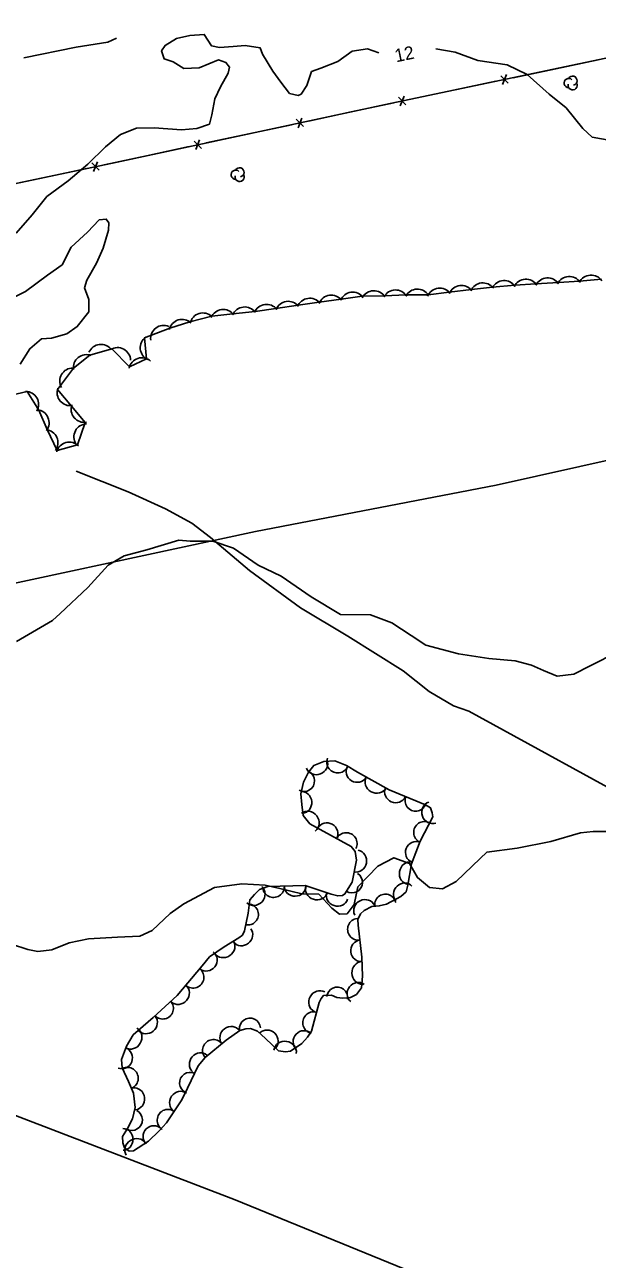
# Model space of a CAD drawing. Extents: x 643342 to 646936, y 5873857 to 5876103.
# Drawn here: x 645445.8 to 645577.3, y 5875329 to 5875612.3 of the extents above; entities that cross this region are included whole.
import ezdxf

# ---------------------------------------------------------------- set-up
doc = ezdxf.new("R2010")
doc.units = 0
for name, color, linetype in [('Niveau 1', 7, 'Continuous'), ('Niveau 2', 7, 'Continuous'), ('Niveau 22', 7, 'Continuous'), ('Niveau 37', 7, 'Continuous'), ('Niveau 4', 7, 'Continuous'), ('Niveau 44', 7, 'Continuous')]:
    doc.layers.add(name, color=color, linetype=linetype)

msp = doc.modelspace()

# ---------------------------------------------------------------- linework, layer by layer
at = {"layer": 'Niveau 1'}
msp.add_lwpolyline([(645443.92, 5875470.79), (645452.23, 5875475.56), (645453.99, 5875477.23), (645460.28, 5875483.15), (645464.96, 5875488.29), (645468.64, 5875490.43), (645473.89, 5875491.77), (645481.2, 5875494), (645483.82, 5875493.82), (645489.02, 5875493.82), (645493.78, 5875492.21), (645499.44, 5875488.28), (645504.69, 5875485.78), (645511.57, 5875481.04), (645518.29, 5875476.93), (645525.21, 5875476.91), (645530.11, 5875475.02), (645534.58, 5875472.16), (645537.95, 5875469.95), (645545.39, 5875467.94), (645552.41, 5875466.89), (645558.39, 5875466.32), (645562.17, 5875465.38), (645564.93, 5875464.11), (645568.04, 5875462.82), (645571.86, 5875463.28), (645575.67, 5875465.19), (645582, 5875468.38)], dxfattribs=at)
at = {"layer": 'Niveau 2'}
for points in [[(645443.86, 5875564.41), (645447.52, 5875568.63), (645450.89, 5875572.83), (645455.82, 5875576.46), (645460.32, 5875580.29), (645464.35, 5875584.24), (645467.84, 5875587.11), (645471.46, 5875588.53), (645475.55, 5875588.6), (645481.82, 5875588.16), (645485.36, 5875588.47), (645488.21, 5875589.48), (645488.82, 5875591.62), (645489.48, 5875595.28), (645490.79, 5875598.01), (645492.53, 5875601.13), (645492.87, 5875602.5), (645492.02, 5875603.58), (645490.35, 5875604.19), (645485.85, 5875602.35), (645482.35, 5875602.21), (645479.9, 5875603.74), (645477.83, 5875604.43), (645477.26, 5875606.24), (645478.07, 5875607.53), (645480.69, 5875609.1)], [(645480.69, 5875609.1), (645483.75, 5875609.77), (645487.06, 5875610.06), (645488.74, 5875607.42), (645490.56, 5875607.06), (645493.71, 5875607.28), (645496.45, 5875607.52), (645499.9, 5875606.95), (645500.43, 5875605.48), (645502.79, 5875601.62), (645504.64, 5875599.05), (645506.65, 5875596.5), (645508.59, 5875596.03), (645509.26, 5875596.32), (645510.58, 5875598.3), (645511.67, 5875601.53), (645513.79, 5875602.3), (645517.69, 5875603.8), (645520.99, 5875606.18), (645524.51, 5875606.72), (645527.15, 5875605.79)], [(645540.18, 5875606.72), (645544.65, 5875605.99), (645549.83, 5875604.06), (645556.59, 5875603.09), (645561.16, 5875600.88), (645566.22, 5875596.33), (645570.13, 5875593.19), (645573.94, 5875588.42), (645576.13, 5875586.46), (645582.55, 5875585.35)], [(645444.75, 5875534.36), (645446.97, 5875537.94), (645449.65, 5875540.21), (645451.95, 5875540.35), (645455.49, 5875541.37), (645457.88, 5875543.03), (645460.52, 5875546.4), (645460.56, 5875549.26), (645459.57, 5875551.9), (645460.05, 5875553.63), (645462.29, 5875557.55), (645463.83, 5875561), (645465.08, 5875565.12), (645465.1, 5875566.81), (645464.56, 5875567.69), (645462.91, 5875567.49), (645460.21, 5875564.69), (645456.49, 5875561.23), (645454.42, 5875557.21), (645451.06, 5875554.81), (645446.03, 5875551.06), (645441.06, 5875548.58)], [(645246.8, 5875436.74), (645309.81, 5875452.91), (645347.57, 5875463.16), (645370.52, 5875468.47), (645498.8, 5875495.97), (645554.04, 5875506.6), (645620.96, 5875521.54), (645671.93, 5875531.75), (645722.29, 5875544.6), (645729.55, 5875514.86), (645737.24, 5875468.76), (645738.05, 5875463.13)], [(645457.63, 5875509.83), (645469.6, 5875505.12), (645478.11, 5875501.19), (645484.21, 5875497.89), (645488.46, 5875494.6), (645497.43, 5875487.09), (645509.15, 5875478.5), (645519.99, 5875471.96), (645532.72, 5875464.05), (645538.71, 5875459.34), (645544.25, 5875456.04), (645547.77, 5875454.79), (645589.95, 5875431.69)], [(645581.41, 5875427.16), (645576.32, 5875427.21), (645573.4, 5875426.9), (645566.63, 5875424.87), (645558.92, 5875423.4), (645551.93, 5875422.48), (645550.42, 5875421.01), (645544.89, 5875415.68), (645541.75, 5875414.04), (645538.76, 5875414.37), (645535.98, 5875416.63), (645534.17, 5875419.87), (645530.6, 5875421.15), (645526.9, 5875419.22), (645522.32, 5875414.46), (645521.43, 5875410.45), (645519.82, 5875408.32), (645518.12, 5875408.2), (645516.32, 5875409.61), (645513.32, 5875412.81), (645509.44, 5875412.87), (645504.41, 5875414.1), (645500.99, 5875414.9), (645495.64, 5875415.18), (645489.41, 5875414.32), (645482.34, 5875410.59), (645479.24, 5875408.38), (645475.08, 5875404.45), (645472.24, 5875403.2), (645467.1, 5875402.96), (645460.48, 5875402.6), (645456.04, 5875401.67), (645452.02, 5875400.02), (645448.87, 5875399.68), (645446.51, 5875400.11), (645442.75, 5875401.34)]]:
    msp.add_lwpolyline(points, dxfattribs=at)
at = {"layer": 'Niveau 22'}
msp.add_lwpolyline([(644607.99, 5875276.54), (644615.34, 5875282.58), (644626.17, 5875289.28), (644635.97, 5875293.95), (644659.53, 5875302.81), (644722.84, 5875328.77), (644742.2, 5875336.13), (644757.56, 5875339.67), (644787.87, 5875347.1), (644846.76, 5875359.49), (644883.37, 5875366.24), (644949.1, 5875380.73), (645027.75, 5875398.1), (645075.65, 5875409.44), (645188.89, 5875433.56), (645246.8, 5875436.74), (645254.39, 5875435.12), (645258.48, 5875433.17), (645290.98, 5875420.13), (645338.2, 5875400.85), (645403.78, 5875377.34), (645494.14, 5875342.72), (645576.71, 5875308.93), (645614.3, 5875294.03)], dxfattribs=at)
at = {"layer": 'Niveau 37'}
for points in [[(645661.64, 5875622.06), (645602.9, 5875609.55), (645529.72, 5875594.18), (645467.05, 5875580.77), (645368.14, 5875559.93), (645217.21, 5875528.14)], [(645577.51, 5875604.21), (645567.73, 5875602.16)], [(645556.81, 5875598.85), (645555.13, 5875600.54)], [(645556.4, 5875600.81), (645555.54, 5875598.58)], [(645567.73, 5875602.16), (645557.94, 5875600.11)], [(645544.24, 5875597.23), (645534.45, 5875595.18)], [(645554.02, 5875599.28), (645544.24, 5875597.23)], [(645530.54, 5875594.36), (645520.76, 5875592.26)], [(645533.32, 5875593.92), (645531.64, 5875595.61)], [(645532.91, 5875595.87), (645532.05, 5875593.65)], [(645520.76, 5875592.26), (645510.98, 5875590.17)], [(645507.07, 5875589.33), (645497.29, 5875587.24)], [(645509.86, 5875588.91), (645508.17, 5875590.59)], [(645509.44, 5875590.86), (645508.59, 5875588.64)], [(645486.39, 5875583.89), (645484.7, 5875585.57)], [(645485.97, 5875585.84), (645485.12, 5875583.61)], [(645497.29, 5875587.24), (645487.51, 5875585.15)], [(645483.6, 5875584.31), (645473.82, 5875582.22)], [(645462.91, 5875578.88), (645461.23, 5875580.57)], [(645462.5, 5875580.83), (645461.64, 5875578.61)], [(645473.82, 5875582.22), (645464.04, 5875580.13)], [(645450.34, 5875577.25), (645440.55, 5875575.19)], [(645460.12, 5875579.31), (645450.34, 5875577.25)]]:
    msp.add_lwpolyline(points, dxfattribs=at)
at = {"layer": 'Niveau 4'}
msp.add_lwpolyline([(645466.89, 5875609.18), (645464.89, 5875608.3), (645457.63, 5875607.09), (645445.62, 5875604.64)], dxfattribs=at)
at = {"layer": 'Niveau 44'}
for points in [[(645578.26, 5875553.88), (645573.19, 5875553.43), (645568.34, 5875553.13), (645563.2, 5875552.8), (645558.36, 5875552.5), (645553.22, 5875552.08), (645548.4, 5875551.5), (645543.29, 5875550.88), (645538.47, 5875550.3), (645533.34, 5875550.27), (645528.49, 5875550.09), (645523.31, 5875550.02), (645518.5, 5875549.34), (645513.41, 5875548.61), (645508.6, 5875547.92), (645503.51, 5875547.2), (645498.7, 5875546.51), (645493.59, 5875545.97), (645488.77, 5875545.41), (645483.76, 5875544.07), (645479.12, 5875542.64), (645473.36, 5875540.41), (645473.8, 5875535.58), (645469.87, 5875533.77), (645465.81, 5875537.9), (645460.79, 5875536.48), (645456.99, 5875533.45), (645453.35, 5875528.6), (645456.56, 5875524.77), (645459.67, 5875521.05), (645457.96, 5875515.86), (645453.27, 5875514.6), (645451.01, 5875519.44), (645449.04, 5875523.88), (645446.35, 5875528.14), (645440.17, 5875526.7)], [(645487.22, 5875375.36), (645492.11, 5875379.28), (645495.22, 5875381.55), (645496.56, 5875381.88), (645497.63, 5875381.99), (645499.26, 5875381.37), (645501.09, 5875379.7), (645504.11, 5875376.87), (645505.71, 5875376.64), (645506.87, 5875376.76), (645509.43, 5875378.58), (645510.76, 5875379.99), (645511.7, 5875381.35), (645513.39, 5875387.98), (645513.88, 5875388.91), (645514.41, 5875389.55), (645516.26, 5875389.64), (645517.49, 5875389.08), (645518.88, 5875388.93), (645520.62, 5875389.1), (645522.02, 5875389.83), (645523.15, 5875391.32), (645523.37, 5875393.98), (645523.22, 5875398.37), (645522.39, 5875405.72), (645522.27, 5875406.98), (645522.92, 5875408.32), (645523.72, 5875409.08), (645525.49, 5875409.95), (645527.24, 5875410.12), (645528.87, 5875410.48), (645532.21, 5875412.28), (645533.37, 5875413.38), (645533.81, 5875414.89), (645534.59, 5875419.76), (645536.62, 5875424.95), (645539.49, 5875430.52), (645539.39, 5875431.49), (645538.99, 5875432.63), (645537.84, 5875433.29), (645529.47, 5875436.75), (645522.21, 5875440.82), (645519.71, 5875442.32), (645517.05, 5875443.43), (645514.52, 5875443.27), (645512.17, 5875442.35), (645510.95, 5875440.76), (645509.81, 5875438.49), (645509.2, 5875435.79), (645509.44, 5875433.37), (645509.79, 5875430.86), (645511.25, 5875428.95), (645520.78, 5875423.75), (645521.68, 5875422.57), (645521.97, 5875420.64), (645521.01, 5875415.56), (645519.33, 5875412.85), (645518.77, 5875412.5), (645517.71, 5875412.39), (645516.2, 5875412.82), (645510.22, 5875414.77), (645501.62, 5875414.59), (645499.73, 5875413.91), (645498.58, 5875412.71), (645497.52, 5875411.53)], [(645497.52, 5875411.53), (645497.14, 5875408.46), (645496.28, 5875404.36), (645495.79, 5875403.43), (645494.97, 5875402.76), (645491.65, 5875400.76), (645488.25, 5875398.47), (645486.6, 5875396.34), (645480.82, 5875389.59), (645475.33, 5875384.48), (645470.71, 5875380.52), (645469.2, 5875377.93), (645468.02, 5875374.89), (645468.2, 5875372.95), (645469.66, 5875369.86), (645470.8, 5875367.14), (645471.21, 5875363.85), (645470.57, 5875361.25), (645469.4, 5875359.09), (645468.31, 5875357.23), (645468.35, 5875355.76), (645468.75, 5875354.63), (645469.8, 5875353.85), (645470.77, 5875353.94), (645474.28, 5875356.13), (645476.7, 5875358.52), (645478.38, 5875360.34), (645481.89, 5875365.66), (645483.2, 5875368.32), (645485.63, 5875373.46), (645487.22, 5875375.36)]]:
    msp.add_lwpolyline(points, dxfattribs=at)
for centre, radius, start, end in [((645570.72, 5875598.89), 1.05, 44.1154, 269.804), ((645571.62, 5875599.42), 1.05, 282.2692, 149.7263), ((645571.62, 5875598.37), 1.05, 166.9369, 29.6212), ((645494.26, 5875577.86), 1.05, 44.1154, 269.804), ((645495.16, 5875577.34), 1.05, 166.9369, 29.6212), ((645495.16, 5875578.39), 1.05, 282.2692, 149.7263), ((645565.88, 5875551.2), 3, 33.6164, 153.5944), ((645565.88, 5875551.2), 3, 33.6164, 153.5944), ((645565.88, 5875551.2), 3, 33.6164, 153.5944), ((645570.87, 5875551.52), 3, 33.6164, 153.5944), ((645570.87, 5875551.52), 3, 33.6164, 153.5944), ((645570.87, 5875551.52), 3, 33.6164, 153.5944), ((645575.86, 5875551.83), 3, 33.6164, 153.5944), ((645575.86, 5875551.83), 3, 33.6164, 153.5944), ((645575.86, 5875551.83), 3, 33.6164, 153.5944), ((645525.98, 5875548.23), 3, 32.206, 152.1839), ((645525.98, 5875548.23), 3, 32.206, 152.1839), ((645525.98, 5875548.23), 3, 32.206, 152.1839), ((645530.98, 5875548.42), 3, 32.206, 152.1839), ((645530.98, 5875548.42), 3, 32.206, 152.1839), ((645530.98, 5875548.42), 3, 32.206, 152.1839), ((645535.98, 5875548.61), 3, 32.206, 152.1839), ((645535.98, 5875548.61), 3, 32.206, 152.1839), ((645535.98, 5875548.61), 3, 32.206, 152.1839), ((645541.09, 5875548.84), 3, 36.9127, 156.8907), ((645541.09, 5875548.84), 3, 36.9127, 156.8907), ((645541.09, 5875548.84), 3, 36.9127, 156.8907), ((645546.06, 5875549.44), 3, 36.9127, 156.8907), ((645546.06, 5875549.44), 3, 36.9127, 156.8907), ((645546.06, 5875549.44), 3, 36.9127, 156.8907), ((645551.02, 5875550.04), 3, 36.9127, 156.8907), ((645551.02, 5875550.04), 3, 36.9127, 156.8907), ((645551.02, 5875550.04), 3, 36.9127, 156.8907), ((645555.9, 5875550.58), 3, 33.6164, 153.5944), ((645555.9, 5875550.58), 3, 33.6164, 153.5944), ((645555.9, 5875550.58), 3, 33.6164, 153.5944), ((645560.89, 5875550.89), 3, 33.6164, 153.5944), ((645560.89, 5875550.89), 3, 33.6164, 153.5944), ((645560.89, 5875550.89), 3, 33.6164, 153.5944), ((645506.3, 5875545.82), 3, 38.133, 158.1109), ((645506.3, 5875545.82), 3, 38.133, 158.1109), ((645506.3, 5875545.82), 3, 38.133, 158.1109), ((645511.25, 5875546.52), 3, 38.133, 158.1109), ((645511.25, 5875546.52), 3, 38.133, 158.1109), ((645511.25, 5875546.52), 3, 38.133, 158.1109), ((645516.2, 5875547.23), 3, 38.133, 158.1109), ((645516.2, 5875547.23), 3, 38.133, 158.1109), ((645516.2, 5875547.23), 3, 38.133, 158.1109), ((645521.15, 5875547.93), 3, 38.133, 158.1109), ((645521.15, 5875547.93), 3, 38.133, 158.1109), ((645521.15, 5875547.93), 3, 38.133, 158.1109), ((645486.74, 5875543.14), 3, 47.0683, 167.0463), ((645486.74, 5875543.14), 3, 47.0683, 167.0463), ((645486.74, 5875543.14), 3, 47.0683, 167.0463), ((645491.38, 5875543.94), 3, 36.6254, 156.6033), ((645491.38, 5875543.94), 3, 36.6254, 156.6033), ((645491.38, 5875543.94), 3, 36.6254, 156.6033), ((645496.35, 5875544.52), 3, 36.6254, 156.6033), ((645496.35, 5875544.52), 3, 36.6254, 156.6033), ((645496.35, 5875544.52), 3, 36.6254, 156.6033), ((645501.35, 5875545.11), 3, 38.133, 158.1109), ((645501.35, 5875545.11), 3, 38.133, 158.1109), ((645501.35, 5875545.11), 3, 38.133, 158.1109), ((645477.73, 5875540.3), 3, 67.3164, 187.2944), ((645477.73, 5875540.3), 3, 67.3164, 187.2944), ((645477.73, 5875540.3), 3, 67.3164, 187.2944), ((645481.96, 5875541.67), 3, 47.0683, 167.0463), ((645481.96, 5875541.67), 3, 47.0683, 167.0463), ((645481.96, 5875541.67), 3, 47.0683, 167.0463), ((645475.34, 5875538.15), 3, 125.1264, 245.1044), ((645475.34, 5875538.15), 3, 125.1264, 245.1044), ((645475.34, 5875538.15), 3, 125.1264, 245.1044), ((645463.34, 5875535.94), 3, 37.0736, 157.0516), ((645463.34, 5875535.94), 3, 37.0736, 157.0516), ((645463.34, 5875535.94), 3, 37.0736, 157.0516), ((645467.13, 5875535.2), 3, 1.9291, 121.907), ((645467.13, 5875535.2), 3, 1.9291, 121.907), ((645467.13, 5875535.2), 3, 1.9291, 121.907), ((645459.99, 5875533.59), 3, 68.5182, 188.4962), ((645459.99, 5875533.59), 3, 68.5182, 188.4962), ((645459.99, 5875533.59), 3, 68.5182, 188.4962), ((645472.73, 5875532.87), 3, 48.4357, 168.4137), ((645472.73, 5875532.87), 3, 48.4357, 168.4137), ((645472.73, 5875532.87), 3, 48.4357, 168.4137), ((645456.86, 5875530.51), 3, 89.4228, 209.4007), ((645456.86, 5875530.51), 3, 89.4228, 209.4007), ((645456.86, 5875530.51), 3, 89.4228, 209.4007), ((645456.26, 5875527.87), 3, 159.9678, 279.9458), ((645456.26, 5875527.87), 3, 159.9678, 279.9458), ((645456.26, 5875527.87), 3, 159.9678, 279.9458), ((645446.02, 5875525.16), 3, 329.718, 89.696), ((645446.02, 5875525.16), 3, 329.718, 89.696), ((645446.02, 5875525.16), 3, 329.718, 89.696), ((645448.42, 5875520.94), 3, 324.0357, 84.0136), ((645448.42, 5875520.94), 3, 324.0357, 84.0136), ((645448.42, 5875520.94), 3, 324.0357, 84.0136), ((645459.47, 5875524.04), 3, 159.9678, 279.9458), ((645459.47, 5875524.04), 3, 159.9678, 279.9458), ((645459.47, 5875524.04), 3, 159.9678, 279.9458), ((645460.12, 5875517.72), 3, 92.4252, 212.4031), ((645460.12, 5875517.72), 3, 92.4252, 212.4031), ((645460.12, 5875517.72), 3, 92.4252, 212.4031), ((645450.45, 5875516.38), 3, 324.0357, 84.0136), ((645450.45, 5875516.38), 3, 324.0357, 84.0136), ((645450.45, 5875516.38), 3, 324.0357, 84.0136), ((645456.07, 5875513.52), 3, 45.0462, 165.0242), ((645456.07, 5875513.52), 3, 45.0462, 165.0242), ((645456.07, 5875513.52), 3, 45.0462, 165.0242)]:
    msp.add_arc(centre, radius, start, end, dxfattribs=at)
for centre, major_axis, ratio, start_param, end_param in [((645517.67, 5875443.12), (-0.91, -2.33), 0.99999, 4.712389, 7.853982), ((645509.93, 5875438.79), (2.16, -1.12), 0.997449, 4.712389, 7.853982), ((645512.86, 5875442.65), (2.38, 0.91), 0.952628, 3.141593, 6.283185), ((645522.09, 5875440.89), (2.12, -1.28), 0.970147, 3.141593, 6.283185), ((645526.52, 5875438.41), (2.27, -1.27), 0.925819, 3.141593, 6.283185), ((645509.43, 5875433.87), (-0.2, 2.49), 0.919919, 3.141593, 6.283185), ((645530.9, 5875436.12), (2.29, -1), 0.919919, 3.141593, 6.283185), ((645535.57, 5875434.27), (-0.95, -2.24), 0.997449, 4.712389, 7.853982), ((645539.41, 5875431.53), (0.84, -2.41), 0.952628, 3.141593, 6.283185), ((645510.95, 5875429.34), (-1.58, 2.06), 0.925819, 3.141593, 6.283185), ((645515.27, 5875426.75), (-2.17, 1.19), 0.970147, 3.141593, 6.283185), ((645537.62, 5875426.99), (-2.24, 1.1), 0.99999, 4.712389, 7.853982), ((645519.65, 5875424.41), (1.15, 2.22), 0.99999, 4.712389, 7.853982), ((645535.65, 5875422.44), (-0.9, -2.3), 0.970147, 3.141593, 6.283185), ((645521.89, 5875420.4), (0.5, 2.5), 0.952628, 3.141593, 6.283185), ((645534.25, 5875417.6), (-0.41, -2.57), 0.925819, 3.141593, 6.283185), ((645520.95, 5875415.53), (2.05, -1.3), 0.997449, 4.712389, 7.853982), ((645532.88, 5875412.98), (-1.85, -1.68), 0.919919, 3.141593, 6.283185), ((645498.54, 5875412.72), (1.72, 1.88), 0.952628, 3.141593, 6.283185), ((645502.93, 5875414.57), (0.1, -2.5), 0.99999, 4.712389, 7.853982), ((645507.9, 5875414.73), (2.47, 0.05), 0.970147, 3.141593, 6.283185), ((645512.84, 5875413.93), (2.47, -0.8), 0.925819, 3.141593, 6.283185), ((645517.54, 5875412.39), (2.39, -0.74), 0.919919, 3.141593, 6.283185), ((645528.62, 5875410.39), (-0.5, 2.38), 0.997449, 4.712389, 7.853982), ((645497.05, 5875408.16), (2.37, -0.53), 0.997449, 4.712389, 7.853982), ((645523.88, 5875409.12), (-2.3, -1.09), 0.952628, 3.141593, 6.283185), ((645522.46, 5875404.75), (-2.48, -0.33), 0.99999, 4.712389, 7.853982), ((645495.74, 5875403.34), (1.96, 1.55), 0.919919, 3.141593, 6.283185), ((645491.55, 5875400.71), (2.15, 1.46), 0.925819, 3.141593, 6.283185), ((645523.07, 5875399.82), (0.28, -2.46), 0.970147, 3.141593, 6.283185), ((645487.58, 5875397.62), (1.52, 1.95), 0.970147, 3.141593, 6.283185), ((645484.45, 5875393.76), (1.93, -1.59), 0.99999, 4.712389, 7.853982), ((645523.35, 5875394.75), (0.09, -2.6), 0.925819, 3.141593, 6.283185), ((645522.21, 5875390.15), (-1.55, -1.96), 0.919919, 3.141593, 6.283185), ((645481.14, 5875390.02), (1.68, 1.92), 0.952628, 3.141593, 6.283185), ((645513.5, 5875388.13), (-1.22, -2.24), 0.952628, 3.141593, 6.283185), ((645517.55, 5875389.04), (0.29, 2.41), 0.997449, 4.712389, 7.853982), ((645477.55, 5875386.59), (1.64, -1.79), 0.997449, 4.712389, 7.853982), ((645473.87, 5875383.17), (1.93, 1.59), 0.919919, 3.141593, 6.283185), ((645497.53, 5875381.95), (-0.22, 2.42), 0.997449, 4.712389, 7.853982), ((645512.16, 5875383.33), (-2.43, 0.57), 0.99999, 4.712389, 7.853982), ((645470.29, 5875379.81), (1.31, 2.24), 0.925819, 3.141593, 6.283185), ((645493.12, 5875379.98), (-2.07, -1.48), 0.952628, 3.141593, 6.283185), ((645501.63, 5875379.25), (-1.79, 1.74), 0.919919, 3.141593, 6.283185), ((645509.89, 5875379.05), (-1.7, -1.8), 0.970147, 3.141593, 6.283185), ((645489.14, 5875376.96), (-1.6, 1.92), 0.99999, 4.712389, 7.853982), ((645505.6, 5875376.65), (-2.57, 0.37), 0.925819, 3.141593, 6.283185), ((645468.14, 5875375.23), (0.89, 2.31), 0.970147, 3.141593, 6.283185), ((645486.02, 5875374), (-1.64, -1.89), 0.919919, 3.141593, 6.283185), ((645469.38, 5875370.57), (2.24, 1.12), 0.99999, 4.712389, 7.853982), ((645483.8, 5875369.51), (-2.19, 1.06), 0.997449, 4.712389, 7.853982), ((645470.92, 5875365.86), (-0.29, 2.53), 0.952628, 3.141593, 6.283185), ((645481.55, 5875365.08), (-1.42, -2.11), 0.952628, 3.141593, 6.283185), ((645470.41, 5875361.03), (2.13, -1.17), 0.997449, 4.712389, 7.853982), ((645478.73, 5875360.95), (-2.11, 1.33), 0.99999, 4.712389, 7.853982), ((645468.37, 5875356.55), (-0.02, 2.5), 0.919919, 3.141593, 6.283185), ((645475.43, 5875357.26), (-1.76, -1.74), 0.970147, 3.141593, 6.283185), ((645471.35, 5875354.29), (-2.2, -1.38), 0.925819, 3.141593, 6.283185)]:
    msp.add_ellipse(centre, major_axis=major_axis, ratio=ratio, start_param=start_param, end_param=end_param, dxfattribs=at)

# ---------------------------------------------------------------- texts
at = {"layer": 'Niveau 2'}
msp.add_text('12', height=3, rotation=11.7366, dxfattribs=at).set_placement((645531.1, 5875603.63))

doc.saveas('drawing.dxf')
